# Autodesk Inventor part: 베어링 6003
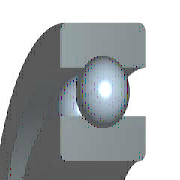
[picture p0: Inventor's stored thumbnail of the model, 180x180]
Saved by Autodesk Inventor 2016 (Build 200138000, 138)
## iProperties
Created: 2012-02
Part Number: 베어링 6003
Material: 강철, 연강
Description: 깊은 그루브 볼 베어링
Document SubType Name: Modeling
Standard: KS B 2023
Designer: mduedu
Standards Organization: KS
Language: ko-KR
Size Designation: 6003 - 17 x 35 x 10
Categories: <MemberInstance><Categories><Category DisplayName="샤프트 부품" InternalName="7f7aeb1f-a693-4053-b835-cee3144e0d98" Mnemonic="SHFT"><Category DisplayName="베어링" Inter
Density: 7.86 g/cm^3
Appearance: 터키옥색
Mass: 39.0276 g
Surface Area: 48.7538 cm^2
Volume: 4.96535 cm^3
IsCustomPart: 1
Author: mduedu
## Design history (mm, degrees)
sketch "스케치" dims "d0" = 4.68 (= -0.26 x WD + 0.26 x BD)
  geometry: L1 (2.66, 13)-(7.34, 13); L2 (5, 13)-(5, 10.66); L3 (5, 13)-(5, 15.34); L4 (3.261, 11.434)-(0, 11.434); L5 (0, 8.5)-(10, 8.5); L6 (3.261, 14.566)-(0, 14.566); L7 (0, 17.5)-(10, 17.5); L8 (10, 8.5)-(10, 11.434); L9 (6.739, 11.434)-(10, 11.434); L10 (6.739, 14.566)-(10, 14.566); L11 (10, 17.5)-(10, 14.566); L12 (-1.4, 0)-(8.4, 0) reference; L13 (0, -0.3)-(0, 5.3) reference
  constraints: 22 end point, 4 point on line, 2 collinear, 2 perpendicular, 2 symmetric about line, 1 midpoint, 1 parallel, 14 other
  dimensions: "d9" = 17 diameter of L5 L12 (= WD); "d11" = 35 diameter of L7 L12 (= BD); "d12" = 10 distance between parallel lines of L8 L13 (= KB); "d13" = 22.868 diameter of L9 L12 (= 0.326 x BD + 0.674 x WD)
revolve "본체" stored, may be unused: angle "d6" = 90 deg
revolve "볼" stored, may be unused: angle "d7" = 90 deg
pattern_circular "IDS_ARRAYBALL[SIMPL:T]" dims angle "d3" = 360 deg
body "Solid1"
fillet "모깎기1" dims "d1" = 0.3 (= KRS)
other parameters: "WD" = 17 [user parameter; used in 5 equation terms], "BD" = 35 [user parameter; used in 5 equation terms], "KB" = 10 [user parameter; used in 1 equation term], "KRS" = 0.3 [user parameter; used in 1 equation term], "d4" = 0, "d5" = 0, "d8" = 0, "d14" = 0, "d15" = 0, "BBA" = 0 [user parameter], "BC0" = 3250000 [user parameter], "BC" = 6050000 [user parameter], "BR" = 17.5 (= 0.5 x BD) [user parameter], "WR" = 8.5 (= 0.5 x WD) [user parameter]
